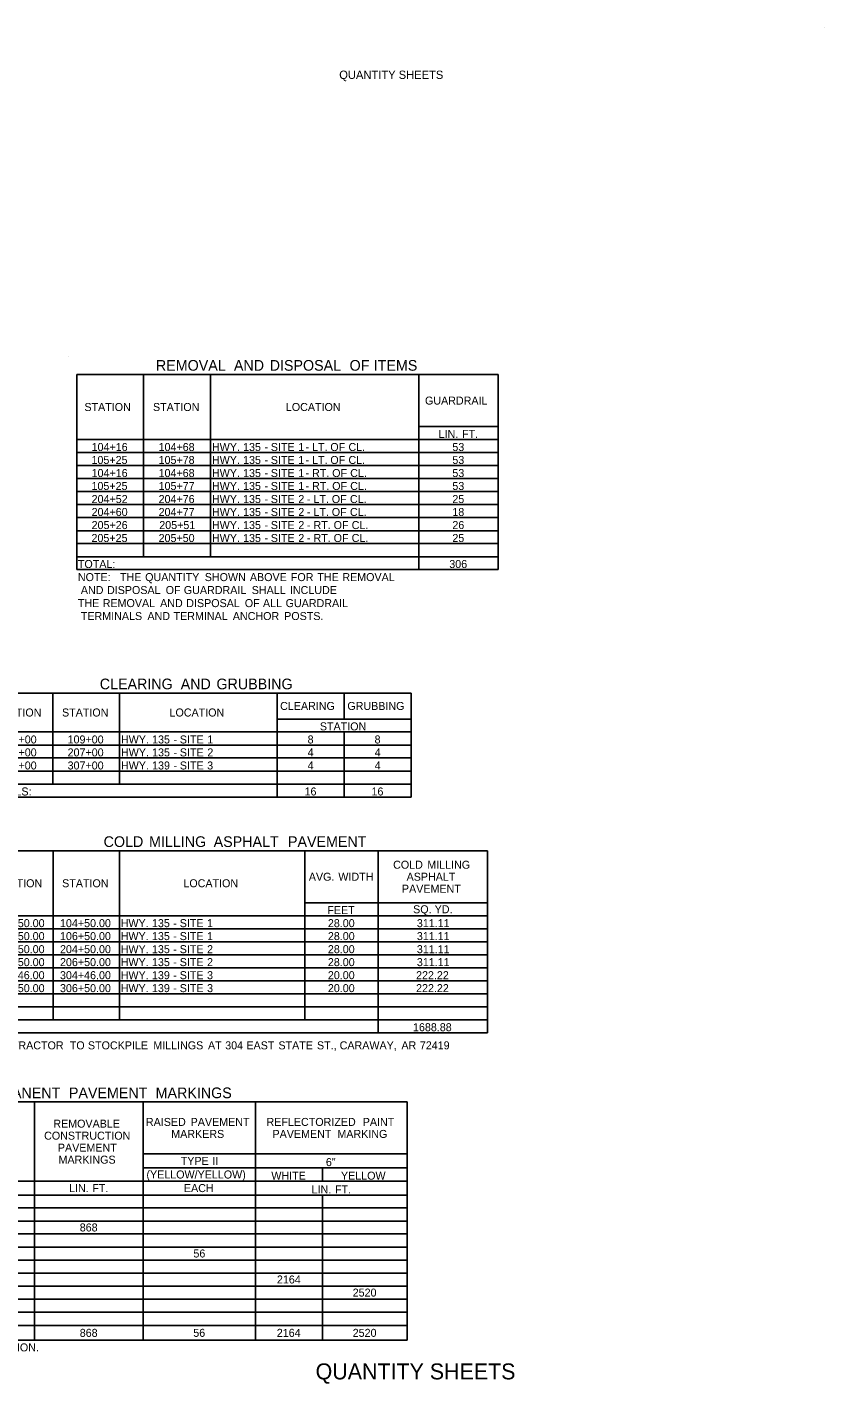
# Model space of a CAD drawing. Extents: x 1955554 to 1962042, y 565952 to 568347.
# Drawn here: x 1958082 to 1958680, y 565984 to 567001 of the extents above; entities that cross this region are included whole.
import ezdxf

# ---------------------------------------------------------------- set-up
doc = ezdxf.new("R2010")
doc.units = 0
for name, color, linetype in [('Default', 7, 'Continuous'), ('R_Border', 7, 'Continuous'), ('STAMP', 7, 'Continuous')]:
    doc.layers.add(name, color=color, linetype=linetype)

msp = doc.modelspace()

# ---------------------------------------------------------------- linework, layer by layer
at = {"layer": 'Default'}
for p, q in [((1958113.7, 566754.4), (1958113.7, 566754.4)), ((1958119.6, 566740.7), (1958435.5, 566740.7)), ((1958119.6, 566594.5), (1958119.6, 566740.7)), ((1958119.6, 566594.5), (1958119.6, 566740.7)), ((1958169.8, 566604.2), (1958169.8, 566740.7)), ((1958220, 566604.2), (1958220, 566740.7)), ((1958376, 566594.5), (1958376, 566740.7)), ((1958435.5, 566594.5), (1958435.5, 566740.7)), ((1958435.5, 566594.5), (1958435.5, 566740.7)), ((1958376, 566701.7), (1958435.5, 566701.7)), ((1958119.6, 566692), (1958435.5, 566692)), ((1958169.8, 566604.2), (1958169.8, 566692)), ((1958220, 566604.2), (1958220, 566692)), ((1958376, 566594.5), (1958376, 566692)), ((1958119.6, 566682.2), (1958435.5, 566682.2)), ((1958119.6, 566672.5), (1958435.5, 566672.5)), ((1958119.6, 566662.7), (1958435.5, 566662.7)), ((1958119.6, 566653), (1958435.5, 566653)), ((1958119.6, 566643.2), (1958435.5, 566643.2)), ((1958119.6, 566633.5), (1958435.5, 566633.5)), ((1958119.6, 566623.7), (1958435.5, 566623.7)), ((1958119.6, 566614), (1958435.5, 566614)), ((1958119.6, 566604.2), (1958435.5, 566604.2)), ((1958376, 566604.2), (1958435.5, 566604.2)), ((1958119.6, 566594.5), (1958435.5, 566594.5)), ((1958051.4, 566502), (1958370.2, 566502)), ((1958101.6, 566433.8), (1958101.6, 566502)), ((1958151.8, 566433.8), (1958151.8, 566502)), ((1958269.8, 566424), (1958269.8, 566502)), ((1958320, 566482.5), (1958320, 566502)), ((1958370.2, 566424), (1958370.2, 566502)), ((1958370.2, 566482.5), (1958370.2, 566502)), ((1958269.8, 566482.5), (1958370.2, 566482.5)), ((1958269.8, 566433.8), (1958269.8, 566482.5)), ((1958051.4, 566472.8), (1958370.2, 566472.8)), ((1958101.6, 566433.8), (1958101.6, 566472.8)), ((1958151.8, 566433.8), (1958151.8, 566472.8)), ((1958320, 566424), (1958320, 566472.8)), ((1958320, 566424), (1958320, 566472.8)), ((1958370.2, 566433.8), (1958370.2, 566472.8)), ((1958051.4, 566463), (1958370.2, 566463)), ((1958051.4, 566453.3), (1958370.2, 566453.3)), ((1958051.4, 566443.5), (1958370.2, 566443.5)), ((1958051.4, 566433.8), (1958370.2, 566433.8)), ((1958151.8, 566433.8), (1958370.2, 566433.8)), ((1958051.4, 566424), (1958370.2, 566424)), ((1958052.2, 566383.8), (1958427.6, 566383.8)), ((1958101.9, 566257.1), (1958101.9, 566383.8)), ((1958151.7, 566257.1), (1958151.7, 566383.8)), ((1958290.6, 566257.1), (1958290.6, 566383.8)), ((1958345.7, 566247.3), (1958345.7, 566383.8)), ((1958427.6, 566247.3), (1958427.6, 566383.8)), ((1958427.6, 566247.3), (1958427.6, 566383.8)), ((1958290.6, 566344.8), (1958427.6, 566344.8)), ((1958290.6, 566257.1), (1958290.6, 566344.8)), ((1958052.2, 566335.1), (1958427.6, 566335.1)), ((1958101.9, 566257.1), (1958101.9, 566335.1)), ((1958151.7, 566257.1), (1958151.7, 566335.1)), ((1958345.7, 566257.1), (1958345.7, 566335.1)), ((1958052.2, 566325.3), (1958427.6, 566325.3)), ((1958052.2, 566315.6), (1958427.6, 566315.6)), ((1958052.2, 566305.8), (1958427.6, 566305.8)), ((1958052.2, 566296.1), (1958427.6, 566296.1)), ((1958052.2, 566286.3), (1958427.6, 566286.3)), ((1958052.2, 566276.6), (1958427.6, 566276.6)), ((1958052.2, 566266.8), (1958427.6, 566266.8)), ((1958052.2, 566257.1), (1958101.9, 566257.1)), ((1958052.2, 566257.1), (1958427.6, 566257.1)), ((1958101.9, 566257.1), (1958151.7, 566257.1)), ((1958151.7, 566257.1), (1958290.6, 566257.1)), ((1958345.7, 566257.1), (1958427.6, 566257.1)), ((1958052.2, 566247.3), (1958427.6, 566247.3)), ((1957521, 566195.5), (1958367.3, 566195.5)), ((1958088, 566017), (1958088, 566195.5)), ((1958169.4, 566017), (1958169.4, 566195.5)), ((1958253.7, 566156.5), (1958253.7, 566195.5)), ((1958253.7, 566017), (1958253.7, 566195.5)), ((1958367.3, 566017), (1958367.3, 566195.5)), ((1958367.3, 566017), (1958367.3, 566195.5)), ((1958169.4, 566156.5), (1958367.3, 566156.5)), ((1958169.4, 566146.2), (1958367.3, 566146.2)), ((1958303.9, 566136), (1958303.9, 566146.2)), ((1957788.6, 566136), (1958367.3, 566136)), ((1958088, 566017), (1958088, 566136)), ((1958169.4, 566017), (1958169.4, 566136)), ((1957521, 566125.7), (1958367.3, 566125.7)), ((1958253.7, 566017), (1958253.7, 566125.7)), ((1958303.9, 566017), (1958303.9, 566125.7)), ((1958303.9, 566017), (1958303.9, 566125.7)), ((1957521, 566116), (1958367.3, 566116)), ((1957521, 566106.2), (1958367.3, 566106.2)), ((1957521, 566096.5), (1958367.3, 566096.5)), ((1957521, 566086.7), (1958367.3, 566086.7)), ((1957521, 566077), (1958367.3, 566077)), ((1957521, 566067.2), (1958367.3, 566067.2)), ((1957521, 566057.5), (1958367.3, 566057.5)), ((1957521, 566047.7), (1958367.3, 566047.7)), ((1957521, 566038), (1958367.3, 566038)), ((1957521, 566027.8), (1958367.3, 566027.8)), ((1957521, 566017), (1958367.3, 566017))]:
    msp.add_line(p, q, dxfattribs=at)
at = {"layer": 'R_Border'}
msp.add_line((1958680.4, 567001.1), (1958680.4, 567001.1), dxfattribs=at)

# ---------------------------------------------------------------- texts
at = {"layer": 'Default'}
for s, height, p in [('REMOVAL', 8, (1958179, 566743.6)), (' AND', 8, (1958234.5, 566743.6)), (' DISPOSAL', 8, (1958261.3, 566743.6)), (' OF', 8, (1958321.2, 566743.6)), (' ITEMS', 8, (1958339.3, 566743.6)), ('GUARDRAIL', 6, (1958380.7, 566718.2)), ('STATION', 6, (1958125.4, 566713.4)), ('STATION', 6, (1958176.8, 566713.4)), ('LOCATION', 6, (1958276.4, 566713.4)), ('LIN.', 6, (1958390.9, 566693.2)), (' FT.', 6, (1958406.2, 566693.2)), ('105+25', 6, (1958130.7, 566673.7)), ('104+16', 6, (1958130.8, 566683.4)), ('104+68', 6, (1958181, 566683.4)), ('105+78', 6, (1958181, 566673.7)), ('HWY.', 6, (1958221, 566683.4)), (' 135', 6, (1958242.1, 566683.4)), (' 135', 6, (1958242.1, 566673.7)), (' -', 6, (1958258.1, 566683.4)), (' SITE', 6, (1958262.9, 566683.4)), (' SITE', 6, (1958262.9, 566673.7)), (' 1', 6, (1958283.5, 566683.4)), (' -', 6, (1958288.9, 566683.4)), (' LT.', 6, (1958293.8, 566683.4)), (' OF', 6, (1958307.5, 566683.4)), (' OF', 6, (1958307.5, 566673.7)), (' CL.', 6, (1958321.1, 566683.4)), (' CL.', 6, (1958321.1, 566673.7)), ('53', 6, (1958401.2, 566683.4)), ('53', 6, (1958401.2, 566673.7)), ('104+16', 6, (1958130.8, 566663.9)), ('104+68', 6, (1958181, 566663.9)), ('HWY.', 6, (1958221, 566673.7)), ('HWY.', 6, (1958221, 566663.9)), (' 135', 6, (1958242.1, 566663.9)), (' -', 6, (1958258.1, 566673.7)), (' SITE', 6, (1958262.9, 566663.9)), (' 1', 6, (1958283.5, 566673.7)), (' 1', 6, (1958283.5, 566663.9)), (' -', 6, (1958288.9, 566673.7)), (' LT.', 6, (1958293.8, 566673.7)), (' RT.', 6, (1958293.8, 566663.9)), (' OF', 6, (1958308.9, 566663.9)), (' CL.', 6, (1958322.4, 566663.9)), ('53', 6, (1958401.2, 566663.9)), ('105+25', 6, (1958130.7, 566654.2)), ('105+77', 6, (1958181, 566654.2)), ('HWY.', 6, (1958221, 566654.2)), (' 135', 6, (1958242.1, 566654.2)), (' -', 6, (1958258.1, 566663.9)), (' SITE', 6, (1958262.9, 566654.2)), (' 1', 6, (1958283.5, 566654.2)), (' -', 6, (1958288.9, 566663.9)), (' RT.', 6, (1958293.8, 566654.2)), (' OF', 6, (1958308.9, 566654.2)), (' CL.', 6, (1958322.4, 566654.2)), ('53', 6, (1958401.2, 566654.2)), ('204+52', 6, (1958130.8, 566644.4)), ('204+76', 6, (1958181, 566644.4)), ('HWY.', 6, (1958221, 566644.4)), (' 135', 6, (1958242.1, 566644.4)), (' -', 6, (1958258.1, 566654.2)), (' SITE', 6, (1958262.9, 566644.4)), (' 2', 6, (1958283.5, 566644.4)), (' -', 6, (1958288.9, 566654.2)), (' LT.', 6, (1958294.9, 566644.4)), (' OF', 6, (1958308.6, 566644.4)), (' CL.', 6, (1958322.2, 566644.4)), ('25', 6, (1958401.2, 566644.4)), ('204+60', 6, (1958130.8, 566634.7)), ('204+77', 6, (1958181, 566634.7)), ('HWY.', 6, (1958221, 566634.7)), (' 135', 6, (1958242.1, 566634.7)), (' -', 6, (1958258.1, 566644.4)), (' SITE', 6, (1958262.9, 566634.7)), (' 2', 6, (1958283.5, 566634.7)), (' -', 6, (1958290, 566644.4)), (' LT.', 6, (1958294.9, 566634.7)), (' OF', 6, (1958308.6, 566634.7)), (' CL.', 6, (1958322.2, 566634.7)), ('18', 6, (1958401.2, 566634.7)), ('205+26', 6, (1958130.8, 566624.9)), ('205+51', 6, (1958181.5, 566624.9)), ('HWY.', 6, (1958221, 566624.9)), (' 135', 6, (1958242.1, 566624.9)), (' -', 6, (1958258.1, 566634.7)), (' SITE', 6, (1958262.9, 566624.9)), (' 2', 6, (1958283.5, 566624.9)), (' -', 6, (1958290, 566634.7)), (' RT.', 6, (1958294.9, 566624.9)), (' OF', 6, (1958310, 566624.9)), (' CL.', 6, (1958323.5, 566624.9)), ('26', 6, (1958401.2, 566624.9)), ('205+25', 6, (1958130.7, 566615.2)), ('205+50', 6, (1958181, 566615.2)), ('HWY.', 6, (1958221, 566615.2)), (' 135', 6, (1958242.1, 566615.2)), (' -', 6, (1958258.1, 566624.9)), (' SITE', 6, (1958262.9, 566615.2)), (' 2', 6, (1958283.5, 566615.2)), (' -', 6, (1958290, 566624.9)), (' RT.', 6, (1958294.9, 566615.2)), (' OF', 6, (1958310, 566615.2)), (' CL.', 6, (1958323.5, 566615.2)), ('25', 6, (1958401.2, 566615.2)), (' -', 6, (1958258.1, 566615.2)), (' -', 6, (1958290, 566615.2)), ('TOTAL:', 6, (1958120.5, 566595.7)), ('306', 6, (1958398.9, 566595.7)), ('NOTE:', 6, (1958120.5, 566585.9)), ('   THE', 6, (1958145.4, 566585.9)), (' QUANTITY', 6, (1958168.7, 566585.9)), (' SHOWN', 6, (1958213.4, 566585.9)), (' ABOVE', 6, (1958247.2, 566585.9)), (' FOR', 6, (1958277.9, 566585.9)), (' THE', 6, (1958297.8, 566585.9)), (' REMOVAL', 6, (1958316.5, 566585.9)), (' AND', 6, (1958120.5, 566576.2)), (' DISPOSAL', 6, (1958140.1, 566576.2)), (' OF', 6, (1958184.1, 566576.2)), (' GUARDRAIL', 6, (1958197.7, 566576.2)), (' SHALL', 6, (1958248.6, 566576.2)), (' INCLUDE', 6, (1958277.2, 566576.2)), ('THE', 6, (1958120.5, 566566.4)), (' REMOVAL', 6, (1958136.9, 566566.4)), (' AND', 6, (1958179.9, 566566.4)), (' DISPOSAL', 6, (1958199.5, 566566.4)), (' OF', 6, (1958243.4, 566566.4)), (' ALL', 6, (1958257, 566566.4)), (' GUARDRAIL', 6, (1958274, 566566.4)), (' TERMINALS', 6, (1958120.5, 566556.7)), (' AND', 6, (1958170.4, 566556.7)), (' TERMINAL', 6, (1958190, 566556.7)), (' ANCHOR', 6, (1958234.4, 566556.7)), (' POSTS.', 6, (1958272.9, 566556.7)), ('CLEARING', 8, (1958136.9, 566504.8)), (' AND', 8, (1958194.6, 566504.8)), (' GRUBBING', 8, (1958221.4, 566504.8)), ('STATION', 6, (1958058.4, 566484.4)), ('STATION', 6, (1958108.6, 566484.4)), ('LOCATION', 6, (1958189.2, 566484.4)), ('CLEARING', 6, (1958272.1, 566489.3)), ('GRUBBING', 6, (1958322.5, 566489.3)), ('STATION', 6, (1958301.9, 566474)), ('101+00', 6, (1958062.6, 566464.2)), ('109+00', 6, (1958112.8, 566464.2)), ('HWY.', 6, (1958152.8, 566464.2)), (' 135', 6, (1958173.9, 566464.2)), (' -', 6, (1958189.9, 566464.2)), (' SITE', 6, (1958194.7, 566464.2)), (' 1', 6, (1958215.3, 566464.2)), ('8', 6, (1958292.7, 566464.2)), ('8', 6, (1958342.9, 566464.2)), ('203+00', 6, (1958062.6, 566454.5)), ('207+00', 6, (1958112.8, 566454.5)), ('HWY.', 6, (1958152.8, 566454.5)), (' 135', 6, (1958173.9, 566454.5)), (' -', 6, (1958189.9, 566454.5)), (' SITE', 6, (1958194.7, 566454.5)), (' 2', 6, (1958215.3, 566454.5)), ('4', 6, (1958292.7, 566454.5)), ('4', 6, (1958343, 566454.5)), ('303+00', 6, (1958062.6, 566444.7)), ('307+00', 6, (1958112.8, 566444.7)), ('HWY.', 6, (1958152.8, 566444.7)), (' 139', 6, (1958173.9, 566444.7)), (' -', 6, (1958189.9, 566444.7)), (' SITE', 6, (1958194.7, 566444.7)), (' 3', 6, (1958215.2, 566444.7)), ('4', 6, (1958292.7, 566444.7)), ('4', 6, (1958343, 566444.7)), ('TOTALS:', 6, (1958052.3, 566425.2)), ('16', 6, (1958290.4, 566425.2)), ('16', 6, (1958340.6, 566425.2)), ('COLD', 8, (1958139.8, 566386.6)), (' MILLING', 8, (1958170.9, 566386.6)), (' ASPHALT', 8, (1958219.3, 566386.6)), (' PAVEMENT', 8, (1958275, 566386.6)), ('COLD', 6, (1958356.8, 566370.3)), (' MILLING', 6, (1958380.2, 566370.3)), ('AVG.', 6, (1958293.6, 566361.3)), (' WIDTH', 6, (1958313.5, 566361.3)), ('ASPHALT', 6, (1958366.9, 566361.3)), ('STATION', 6, (1958059, 566356.4)), ('STATION', 6, (1958108.7, 566356.4)), ('LOCATION', 6, (1958199.6, 566356.4)), ('PAVEMENT', 6, (1958363.4, 566352.3)), ('FEET', 6, (1958307.5, 566336.3)), ('SQ.', 6, (1958371.8, 566336.9)), (' YD.', 6, (1958385.7, 566336.9)), ('103+50.00', 6, (1958057.4, 566326.5)), ('104+50.00', 6, (1958107.1, 566326.5)), ('HWY.', 6, (1958152.6, 566326.5)), (' 135', 6, (1958173.8, 566326.5)), (' -', 6, (1958189.8, 566326.5)), (' SITE', 6, (1958194.6, 566326.5)), (' 1', 6, (1958215.1, 566326.5)), ('28.00', 6, (1958307.9, 566326.5)), ('311.11', 6, (1958374.6, 566326.5)), ('105+50.00', 6, (1958057.4, 566316.8)), ('106+50.00', 6, (1958107.1, 566316.8)), ('HWY.', 6, (1958152.6, 566316.8)), (' 135', 6, (1958173.8, 566316.8)), (' -', 6, (1958189.8, 566316.8)), (' SITE', 6, (1958194.6, 566316.8)), (' 1', 6, (1958215.1, 566316.8)), ('28.00', 6, (1958307.9, 566316.8)), ('311.11', 6, (1958374.6, 566316.8)), ('203+50.00', 6, (1958057.4, 566307)), ('204+50.00', 6, (1958107.1, 566307)), ('HWY.', 6, (1958152.6, 566307)), (' 135', 6, (1958173.8, 566307)), (' -', 6, (1958189.8, 566307)), (' SITE', 6, (1958194.6, 566307)), (' 2', 6, (1958215.1, 566307)), ('28.00', 6, (1958307.9, 566307)), ('311.11', 6, (1958374.6, 566307)), ('303+46.00', 6, (1958057.4, 566287.5)), ('205+50.00', 6, (1958057.4, 566297.3)), ('304+46.00', 6, (1958107.1, 566287.5)), ('206+50.00', 6, (1958107.1, 566297.3)), ('HWY.', 6, (1958152.6, 566297.3)), ('HWY.', 6, (1958152.6, 566287.5)), (' 135', 6, (1958173.8, 566297.3)), (' 139', 6, (1958173.8, 566287.5)), (' -', 6, (1958189.8, 566297.3)), (' SITE', 6, (1958194.6, 566297.3)), (' SITE', 6, (1958194.6, 566287.5)), (' 3', 6, (1958215.1, 566287.5)), (' 2', 6, (1958215.1, 566297.3)), ('28.00', 6, (1958307.9, 566297.3)), ('20.00', 6, (1958307.9, 566287.5)), ('222.22', 6, (1958374, 566287.5)), ('311.11', 6, (1958374.6, 566297.3)), ('305+50.00', 6, (1958057.4, 566277.8)), ('306+50.00', 6, (1958107.1, 566277.8)), ('HWY.', 6, (1958152.6, 566277.8)), (' 139', 6, (1958173.8, 566277.8)), (' -', 6, (1958189.7, 566287.5)), (' SITE', 6, (1958194.6, 566277.8)), (' 3', 6, (1958215.1, 566277.8)), ('20.00', 6, (1958307.9, 566277.8)), ('222.22', 6, (1958374, 566277.8)), (' -', 6, (1958189.7, 566277.8)), ('1688.88', 6, (1958371.7, 566248.5)), ('CONTRACTOR', 6, (1958053.2, 566234.9)), (' TO', 6, (1958112.2, 566234.9)), (' STOCKPILE', 6, (1958125.8, 566234.9)), (' MILLINGS', 6, (1958174.8, 566234.9)), (' AT', 6, (1958215.8, 566234.9)), (' 304', 6, (1958228.7, 566234.9)), (' EAST', 6, (1958244.6, 566234.9)), (' STATE', 6, (1958268.6, 566234.9)), (' ST.,', 6, (1958297.5, 566234.9)), (' CARAWAY,', 6, (1958314.5, 566234.9)), (' AR', 6, (1958360.8, 566234.9)), (' 72419', 6, (1958374.6, 566234.9)), (' PERMANENT', 8, (1958037.2, 566198.3)), (' PAVEMENT', 8, (1958110.8, 566198.3)), (' MARKINGS', 8, (1958175.8, 566198.3)), ('REMOVABLE', 6, (1958102.1, 566176.2)), ('RAISED', 6, (1958171.5, 566177.5)), (' PAVEMENT', 6, (1958202.8, 566177.5)), ('REFLECTORIZED', 6, (1958261.9, 566177.5)), (' PAINT', 6, (1958331.8, 566177.5)), ('CONSTRUCTION', 6, (1958095.2, 566167.2)), ('MARKERS', 6, (1958190.5, 566168.5)), ('PAVEMENT', 6, (1958266.4, 566168.5)), (' MARKING', 6, (1958312.8, 566168.5)), ('PAVEMENT', 6, (1958105.5, 566158.2)), ('MARKINGS', 6, (1958106, 566149.2)), ('TYPE', 6, (1958197.6, 566148.3)), (' II', 6, (1958219.1, 566148.3)), ('6"', 6, (1958306.4, 566147.4)), ('(YELLOW/YELLOW)', 6, (1958171.9, 566138.1)), ('WHITE', 6, (1958265.5, 566137.2)), ('YELLOW', 6, (1958317.7, 566137.2)), ('LIN.', 6, (1958113.9, 566127.9)), (' FT.', 6, (1958129.1, 566127.9)), ('EACH', 6, (1958200, 566127.9)), ('LIN.', 6, (1958295.7, 566126.9)), (' FT.', 6, (1958311, 566126.9)), ('868', 6, (1958121.9, 566098.4)), ('56', 6, (1958207.1, 566078.9)), ('2164', 6, (1958269.7, 566059.4)), ('2520', 6, (1958326.5, 566049.6)), ('868', 6, (1958121.9, 566019.4)), ('56', 6, (1958207, 566019.4)), ('2164', 6, (1958269.6, 566019.4)), ('2520', 6, (1958326.5, 566019.4)), (' CONSTRUCTION.', 6, (1958022.2, 566008.5))]:
    msp.add_text(s, height=height, dxfattribs=at).set_placement(p)
at = {"layer": 'R_Border'}
msp.add_text('QUANTITY SHEETS', height=12, rotation=0, dxfattribs=at).set_placement((1958298.7, 565987.5))
at = {"layer": 'STAMP'}
msp.add_text('QUANTITY SHEETS', height=6.25, rotation=360, dxfattribs=at).set_placement((1958316.4, 566962.3))

doc.saveas('drawing.dxf')
